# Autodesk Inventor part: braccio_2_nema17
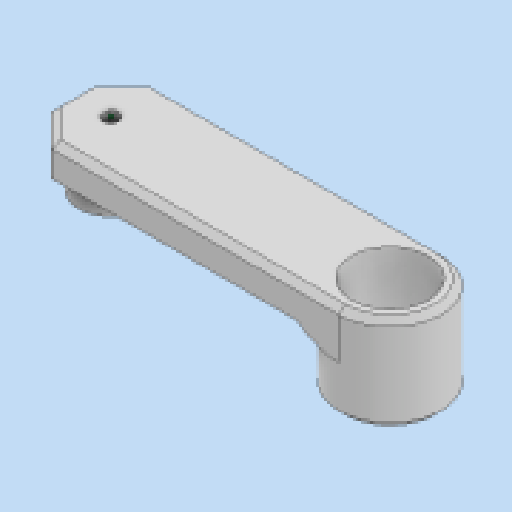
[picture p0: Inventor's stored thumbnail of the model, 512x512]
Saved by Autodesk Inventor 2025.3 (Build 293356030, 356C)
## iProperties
Created: 2025-11
Part Number: braccio_2_nema17
Material: Generico
Document SubType Name: Modeling
Designer: R5800u
Density: 1 g/cm^3
Appearance: Default
Author: R5800u
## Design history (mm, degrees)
sketch "Schizzo1"
  geometry: L1 (2, 1.582)-(2, -1.582); C1 r 10 at (0, 0); A1 r 2.55 centre (0, 0) between (2, 1.582) and (2, -1.582); 1 further point
  constraints: 2 centre point, 2 coincident, 2 end point, 2 point on circle, 1 vertical
  dimensions: "d0" = 20 diameter of C1; "d1" = 5.1 diameter of A1; "d2" = 2 distance from line of point (0, 0) L1
extrude "Estrusione1" new body sketch "Schizzo1" distance "d3" = 20; taper "d4" = 0 deg
sketch "Schizzo2"
  geometry: L1 (-12.5, -16)-(87.5, -16); L2 (87.5, -16)-(87.5, 16); L3 (87.5, 16)-(-12.5, 16); L4 (-12.5, 16)-(-12.5, -16); L5 (0, 0)-(107, 0) reference; C1 r 10 at (0, 0) reference; C2 r 2.55 at (0, 0) reference; 1 further point
  constraints: 10 end point, 3 horizontal, 2 parallel, 1 perpendicular, 1 other
  dimensions: "d5" = 100 distance of L3.end L2.end
extrude "Estrusione2" join sketch "Schizzo2" distance "d6" = 10; taper "d7" = 0 deg
sketch "Schizzo3"
  geometry: L1 (18.5, -5)-(13.5, -5); L2 (13.5, -5)-(13.5, -15); L3 (13.5, -15)-(18.5, -15); L4 (18.5, -15)-(18.5, -5); L5 (6, -10)-(26, -10) reference; L6 (18.5, -5)-(13.5, -15); L7 (13.5, -5)-(18.5, -15); L8 (32, -10)-(0, -10) reference; 4 further points
  constraints: 12 end point, 3 midpoint, 2 parallel, 1 horizontal, 1 perpendicular
  dimensions: "d8" = 5 distance of L3.end L2.end
extrude "Estrusione3" join sketch "Schizzo3" stored distance "d9" = 10; taper "d10" = 0 deg
chamfer "Smusso1" distance "d11" = 10; stored, may be unused: second distance "d12" = 2, angle "d13" = 45 deg
sketch "Schizzo4"
  geometry: L1 (87.5, -2.5)-(87.5, 2.5) reference; L2 (87.5, -16)-(87.5, 16) reference; 2 further points
  constraints: 1 midpoint, 1 vertical alignment, 2 other
extrude "Estrusione4" join sketch "Schizzo4" distance "d14" = 30; taper "d15" = 0 deg
sketch "Schizzo5"
  geometry: C1 r 1.6 at (87.5, -7) reference; C2 r 1.6 at (87.5, 7) reference; C3 r 1.6 at (94.5, 0) reference; C4 r 1.6 at (80.5, 0) reference; C5 r 3 at (87.5, 0) reference; C6 r 12 at (87.5, 0); 1 further point
  constraints: 1 centre point, 1 coincident
extrude "Estrusione5" cut sketch "Schizzo5" distance "d16" = 26; taper "d17" = 0 deg
sketch "Schizzo6"
  geometry: C1 r 1.25 at (0, 0) reference; C2 r 1.6 at (0, -7) reference; C3 r 1.6 at (7, 0) reference; C4 r 1.6 at (-7, 0) reference; C5 r 1.6 at (0, 7) reference; 1 further point
extrude "Estrusione6" cut sketch "Schizzo6" distance "d18" = 26; taper "d19" = 0 deg
chamfer "Smusso2" distance "d20" = 2; stored, may be unused: second distance "d21" = 2, angle "d22" = 45 deg
chamfer "Smusso3" distance "d23" = 5; stored, may be unused: second distance "d24" = 2, angle "d25" = 45 deg
sketch "Schizzo7"
  geometry: 1 further point
sketch "Schizzo8"
  geometry: L1 (-2, 1.582)-(-2, -1.582); A1 r 2.55 centre (0, 0) between (-2, 1.582) and (-2, -1.582) reference; 1 further point
  constraints: 2 end point, 2 point on circle, 1 vertical
  dimensions: "d29" = 2 distance from line of point (0, 0) L1
extrude "Estrusione7" join sketch "Schizzo8" distance "d30" = 17; taper "d31" = 0 deg
fillet "Raccordo1" dims "d32" = 2
sketch "Schizzo9"
  geometry: L1 (-2.5, -16)-(87.5, -16) reference; L2 (11, -16)-(76.5, -16); L3 (76.5, -16)-(76.5, -13); L4 (76.5, -13)-(11, -13); L5 (11, -13)-(11, -16); C1 r 1.25 at (87.5, 0) reference; 2 further points
  constraints: 8 end point, 2 parallel, 1 horizontal, 1 perpendicular, 1 point on line
  dimensions: "d33" = 11 distance from line of point (0, 0) L5; "d34" = 11 distance from line of C1.centre L3
extrude "Estrusione8" cut sketch "Schizzo9" extent not by distance; stored distance "d35" = 0; taper "d36" = 0 deg
mirror "Speculare1"
chamfer "Smusso5" distance "d37" = 3; stored, may be unused: second distance "d38" = 2, angle "d39" = 45 deg
chamfer "Smusso6" distance "d40" = 2; stored, may be unused: second distance "d41" = 2, angle "d42" = 45 deg
node "Solido1"
node "Linea chiusa proiettata1"
node "Riferimento1"
node "Riferimento2"
node "Riferimento3"
node "Riferimento4"
node "Riferimento5"
node "Riferimento6"
node "Riferimento7"
node "Riferimento8"
node "Riferimento9"
node "Riferimento10"
